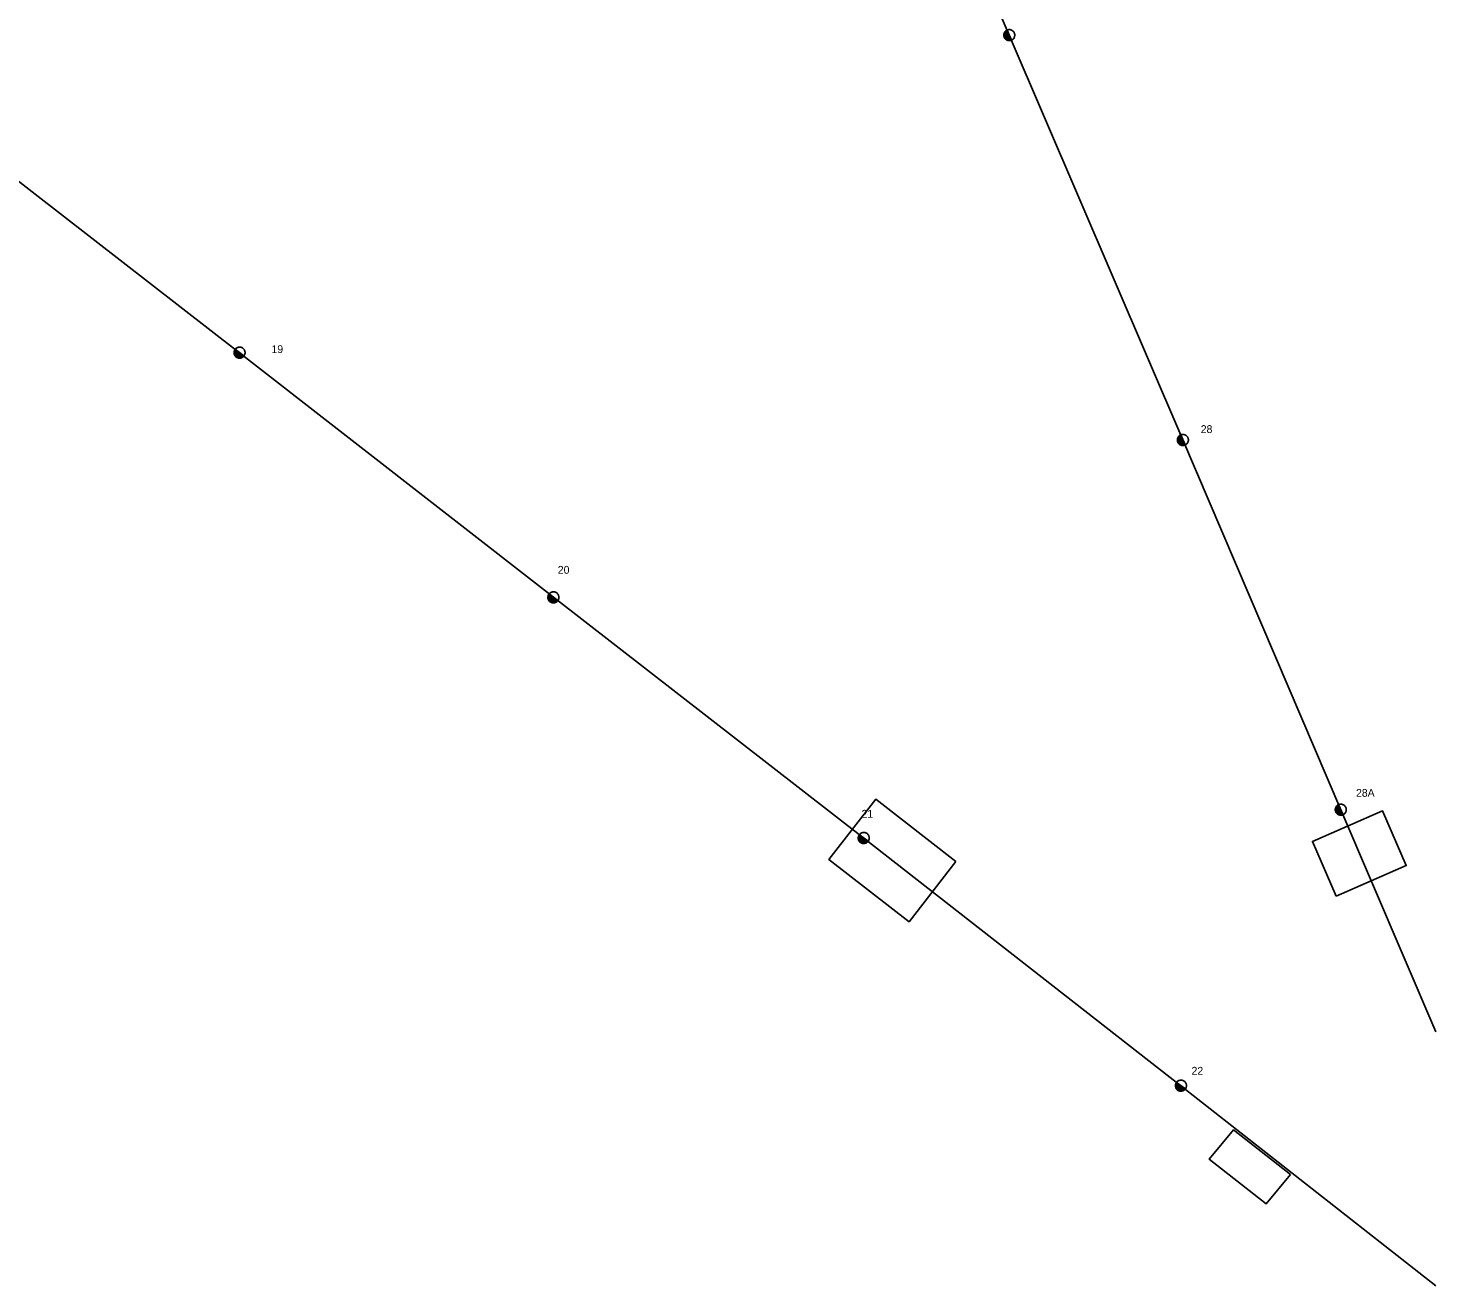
# Model space of a CAD drawing. Extents: x -762500 to -761250, y -1155000 to -1154000.
# Drawn here: x -761563.4 to -761250, y -1154560 to -1154280 of the extents above; entities that cross this region are included whole.
import ezdxf

# ---------------------------------------------------------------- set-up
doc = ezdxf.new("R2010")
doc.units = 0
for name, color, linetype in [('Vrstva 1', 7, 'Continuous'), ('Vrstva 13', 7, 'Continuous'), ('Vrstva 14', 7, 'Continuous'), ('Vrstva 35', 7, 'Continuous')]:
    doc.layers.add(name, color=color, linetype=linetype)

msp = doc.modelspace()

# ---------------------------------------------------------------- linework, layer by layer
at = {"layer": 'Vrstva 1'}
for points in [[(-761405.34, -1154140.88), (-761379.44, -1154200.97), (-761344.97, -1154281.58), (-761306.31, -1154371.71), (-761271.16, -1154454.04), (-761250, -1154503.48)], [(-761670.23, -1154232.75), (-761595.45, -1154290.91), (-761516.33, -1154352.27), (-761446.46, -1154406.74), (-761377.37, -1154460.33), (-761306.74, -1154515.48), (-761250, -1154560.04)]]:
    msp.add_lwpolyline(points, dxfattribs=at)
at = {"layer": 'Vrstva 13'}
for points in [[(-761344.477, -1154282.695), (-761344.362, -1154282.637), (-761344.255, -1154282.567), (-761344.155, -1154282.486), (-761344.064, -1154282.395), (-761343.983, -1154282.295), (-761343.913, -1154282.187), (-761343.855, -1154282.073), (-761343.808, -1154281.953), (-761343.775, -1154281.829), (-761343.755, -1154281.701), (-761343.748, -1154281.573), (-761343.755, -1154281.445), (-761343.775, -1154281.318), (-761343.808, -1154281.193), (-761343.855, -1154281.073), (-761343.913, -1154280.959), (-761343.983, -1154280.851), (-761344.064, -1154280.751), (-761344.154, -1154280.66), (-761344.254, -1154280.579), (-761344.362, -1154280.509), (-761344.477, -1154280.451), (-761344.597, -1154280.405), (-761344.721, -1154280.371), (-761344.848, -1154280.352), (-761344.976, -1154280.345), (-761345.105, -1154280.351), (-761345.232, -1154280.372), (-761345.356, -1154280.405), (-761345.476, -1154280.451), (-761345.591, -1154280.509), (-761345.699, -1154280.579), (-761345.799, -1154280.66), (-761345.89, -1154280.752), (-761345.97, -1154280.851), (-761346.04, -1154280.959), (-761346.099, -1154281.073), (-761346.145, -1154281.194), (-761346.178, -1154281.318), (-761346.199, -1154281.445), (-761346.205, -1154281.573), (-761346.198, -1154281.701), (-761346.178, -1154281.828), (-761346.145, -1154281.953), (-761346.099, -1154282.073), (-761346.041, -1154282.187), (-761345.97, -1154282.295), (-761345.889, -1154282.395), (-761345.799, -1154282.486), (-761345.699, -1154282.567), (-761345.591, -1154282.637), (-761345.476, -1154282.696), (-761345.356, -1154282.741), (-761345.232, -1154282.774), (-761345.105, -1154282.795), (-761344.977, -1154282.802), (-761344.848, -1154282.795), (-761344.721, -1154282.774), (-761344.597, -1154282.741), (-761344.477, -1154282.695)], [(-761346.109, -1154281.275), (-761345.532, -1154282.572)], [(-761345.955, -1154280.912), (-761345.151, -1154282.718)], [(-761345.762, -1154280.638), (-761344.834, -1154282.724)], [(-761345.471, -1154280.444), (-761344.471, -1154282.689)], [(-761515.359, -1154353.006), (-761515.287, -1154352.899), (-761515.226, -1154352.786), (-761515.178, -1154352.667), (-761515.142, -1154352.543), (-761515.12, -1154352.417), (-761515.112, -1154352.288), (-761515.116, -1154352.16), (-761515.133, -1154352.033), (-761515.165, -1154351.908), (-761515.209, -1154351.787), (-761515.265, -1154351.671), (-761515.333, -1154351.562), (-761515.413, -1154351.461), (-761515.502, -1154351.368), (-761515.6, -1154351.286), (-761515.707, -1154351.214), (-761515.82, -1154351.154), (-761515.94, -1154351.105), (-761516.063, -1154351.07), (-761516.19, -1154351.047), (-761516.318, -1154351.039), (-761516.447, -1154351.043), (-761516.574, -1154351.061), (-761516.699, -1154351.092), (-761516.819, -1154351.136), (-761516.935, -1154351.192), (-761517.044, -1154351.26), (-761517.146, -1154351.34), (-761517.238, -1154351.429), (-761517.321, -1154351.528), (-761517.393, -1154351.634), (-761517.453, -1154351.748), (-761517.501, -1154351.867), (-761517.536, -1154351.991), (-761517.559, -1154352.117), (-761517.568, -1154352.245), (-761517.563, -1154352.374), (-761517.545, -1154352.501), (-761517.514, -1154352.626), (-761517.47, -1154352.747), (-761517.414, -1154352.863), (-761517.346, -1154352.971), (-761517.267, -1154353.073), (-761517.177, -1154353.165), (-761517.079, -1154353.248), (-761516.972, -1154353.32), (-761516.859, -1154353.38), (-761516.739, -1154353.428), (-761516.616, -1154353.464), (-761516.49, -1154353.486), (-761516.361, -1154353.495), (-761516.232, -1154353.491), (-761516.105, -1154353.472), (-761515.98, -1154353.441), (-761515.86, -1154353.398), (-761515.744, -1154353.341), (-761515.635, -1154353.273), (-761515.534, -1154353.194), (-761515.441, -1154353.105), (-761515.359, -1154353.006)], [(-761517.516, -1154352.163), (-761515.937, -1154353.353)], [(-761517.48, -1154351.83), (-761515.656, -1154353.204)], [(-761517.474, -1154352.555), (-761516.34, -1154353.41)], [(-761517.319, -1154351.519), (-761515.357, -1154352.998)], [(-761305.818, -1154372.825), (-761305.703, -1154372.766), (-761305.595, -1154372.696), (-761305.495, -1154372.615), (-761305.404, -1154372.525), (-761305.323, -1154372.425), (-761305.253, -1154372.317), (-761305.195, -1154372.202), (-761305.149, -1154372.083), (-761305.115, -1154371.958), (-761305.095, -1154371.831), (-761305.088, -1154371.703), (-761305.096, -1154371.574), (-761305.116, -1154371.447), (-761305.149, -1154371.323), (-761305.195, -1154371.203), (-761305.253, -1154371.089), (-761305.323, -1154370.981), (-761305.404, -1154370.881), (-761305.495, -1154370.79), (-761305.595, -1154370.709), (-761305.703, -1154370.639), (-761305.817, -1154370.58), (-761305.938, -1154370.534), (-761306.062, -1154370.501), (-761306.189, -1154370.481), (-761306.317, -1154370.474), (-761306.445, -1154370.481), (-761306.573, -1154370.501), (-761306.697, -1154370.534), (-761306.817, -1154370.58), (-761306.931, -1154370.639), (-761307.039, -1154370.709), (-761307.139, -1154370.79), (-761307.23, -1154370.881), (-761307.311, -1154370.981), (-761307.381, -1154371.088), (-761307.439, -1154371.203), (-761307.485, -1154371.323), (-761307.519, -1154371.447), (-761307.539, -1154371.574), (-761307.545, -1154371.703), (-761307.539, -1154371.831), (-761307.519, -1154371.958), (-761307.485, -1154372.083), (-761307.439, -1154372.202), (-761307.381, -1154372.317), (-761307.311, -1154372.424), (-761307.23, -1154372.525), (-761307.139, -1154372.616), (-761307.039, -1154372.696), (-761306.931, -1154372.767), (-761306.817, -1154372.825), (-761306.697, -1154372.871), (-761306.572, -1154372.904), (-761306.445, -1154372.924), (-761306.317, -1154372.931), (-761306.189, -1154372.924), (-761306.062, -1154372.904), (-761305.938, -1154372.871), (-761305.818, -1154372.825)], [(-761307.45, -1154371.405), (-761306.872, -1154372.702)], [(-761307.296, -1154371.042), (-761306.492, -1154372.848)], [(-761307.103, -1154370.767), (-761306.174, -1154372.854)], [(-761306.811, -1154370.574), (-761305.812, -1154372.818)], [(-761445.489, -1154407.476), (-761445.417, -1154407.369), (-761445.356, -1154407.256), (-761445.308, -1154407.137), (-761445.272, -1154407.013), (-761445.25, -1154406.887), (-761445.242, -1154406.758), (-761445.246, -1154406.63), (-761445.263, -1154406.503), (-761445.295, -1154406.378), (-761445.339, -1154406.257), (-761445.395, -1154406.141), (-761445.463, -1154406.032), (-761445.543, -1154405.931), (-761445.632, -1154405.838), (-761445.73, -1154405.756), (-761445.837, -1154405.684), (-761445.95, -1154405.624), (-761446.07, -1154405.575), (-761446.193, -1154405.54), (-761446.32, -1154405.517), (-761446.448, -1154405.509), (-761446.577, -1154405.513), (-761446.704, -1154405.531), (-761446.829, -1154405.562), (-761446.949, -1154405.606), (-761447.065, -1154405.662), (-761447.174, -1154405.73), (-761447.276, -1154405.81), (-761447.368, -1154405.899), (-761447.451, -1154405.998), (-761447.523, -1154406.104), (-761447.583, -1154406.218), (-761447.631, -1154406.337), (-761447.666, -1154406.461), (-761447.689, -1154406.587), (-761447.698, -1154406.715), (-761447.693, -1154406.844), (-761447.675, -1154406.971), (-761447.644, -1154407.096), (-761447.6, -1154407.217), (-761447.544, -1154407.333), (-761447.476, -1154407.441), (-761447.397, -1154407.543), (-761447.307, -1154407.635), (-761447.209, -1154407.718), (-761447.102, -1154407.79), (-761446.989, -1154407.85), (-761446.869, -1154407.898), (-761446.746, -1154407.934), (-761446.62, -1154407.956), (-761446.491, -1154407.965), (-761446.362, -1154407.961), (-761446.235, -1154407.942), (-761446.11, -1154407.911), (-761445.989, -1154407.868), (-761445.874, -1154407.811), (-761445.765, -1154407.743), (-761445.664, -1154407.664), (-761445.571, -1154407.575), (-761445.489, -1154407.476)], [(-761447.646, -1154406.633), (-761446.067, -1154407.823)], [(-761447.61, -1154406.3), (-761445.786, -1154407.674)], [(-761447.604, -1154407.025), (-761446.47, -1154407.88)], [(-761447.449, -1154405.989), (-761445.487, -1154407.468)], [(-761270.667, -1154455.155), (-761270.552, -1154455.097), (-761270.445, -1154455.027), (-761270.345, -1154454.946), (-761270.254, -1154454.855), (-761270.173, -1154454.755), (-761270.103, -1154454.647), (-761270.045, -1154454.533), (-761269.998, -1154454.413), (-761269.965, -1154454.289), (-761269.945, -1154454.161), (-761269.938, -1154454.033), (-761269.945, -1154453.905), (-761269.965, -1154453.777), (-761269.998, -1154453.653), (-761270.045, -1154453.533), (-761270.103, -1154453.419), (-761270.173, -1154453.311), (-761270.254, -1154453.211), (-761270.345, -1154453.12), (-761270.445, -1154453.039), (-761270.552, -1154452.969), (-761270.667, -1154452.911), (-761270.787, -1154452.865), (-761270.912, -1154452.831), (-761271.038, -1154452.812), (-761271.166, -1154452.805), (-761271.295, -1154452.811), (-761271.422, -1154452.832), (-761271.546, -1154452.865), (-761271.666, -1154452.911), (-761271.781, -1154452.969), (-761271.889, -1154453.039), (-761271.989, -1154453.12), (-761272.08, -1154453.212), (-761272.16, -1154453.311), (-761272.23, -1154453.419), (-761272.289, -1154453.533), (-761272.335, -1154453.653), (-761272.368, -1154453.778), (-761272.389, -1154453.905), (-761272.395, -1154454.033), (-761272.388, -1154454.161), (-761272.368, -1154454.288), (-761272.335, -1154454.413), (-761272.289, -1154454.533), (-761272.231, -1154454.647), (-761272.161, -1154454.755), (-761272.079, -1154454.855), (-761271.989, -1154454.946), (-761271.889, -1154455.027), (-761271.781, -1154455.097), (-761271.666, -1154455.156), (-761271.546, -1154455.201), (-761271.422, -1154455.234), (-761271.295, -1154455.255), (-761271.167, -1154455.262), (-761271.038, -1154455.255), (-761270.911, -1154455.234), (-761270.787, -1154455.201), (-761270.667, -1154455.155)], [(-761272.299, -1154453.735), (-761271.722, -1154455.032)], [(-761272.145, -1154453.372), (-761271.341, -1154455.178)], [(-761271.953, -1154453.098), (-761271.024, -1154455.184)], [(-761271.661, -1154452.904), (-761270.662, -1154455.149)], [(-761376.399, -1154461.066), (-761376.327, -1154460.959), (-761376.267, -1154460.846), (-761376.218, -1154460.727), (-761376.183, -1154460.603), (-761376.16, -1154460.477), (-761376.152, -1154460.348), (-761376.156, -1154460.22), (-761376.174, -1154460.093), (-761376.205, -1154459.968), (-761376.249, -1154459.847), (-761376.305, -1154459.731), (-761376.373, -1154459.622), (-761376.453, -1154459.521), (-761376.542, -1154459.428), (-761376.641, -1154459.346), (-761376.747, -1154459.274), (-761376.861, -1154459.214), (-761376.98, -1154459.165), (-761377.103, -1154459.13), (-761377.23, -1154459.107), (-761377.358, -1154459.099), (-761377.487, -1154459.103), (-761377.614, -1154459.121), (-761377.739, -1154459.152), (-761377.859, -1154459.196), (-761377.975, -1154459.252), (-761378.084, -1154459.32), (-761378.186, -1154459.4), (-761378.278, -1154459.489), (-761378.361, -1154459.588), (-761378.433, -1154459.694), (-761378.493, -1154459.808), (-761378.541, -1154459.927), (-761378.576, -1154460.051), (-761378.599, -1154460.177), (-761378.608, -1154460.305), (-761378.603, -1154460.434), (-761378.585, -1154460.561), (-761378.554, -1154460.686), (-761378.511, -1154460.807), (-761378.454, -1154460.923), (-761378.386, -1154461.031), (-761378.307, -1154461.133), (-761378.217, -1154461.225), (-761378.119, -1154461.308), (-761378.012, -1154461.38), (-761377.899, -1154461.44), (-761377.78, -1154461.488), (-761377.656, -1154461.524), (-761377.53, -1154461.546), (-761377.401, -1154461.555), (-761377.272, -1154461.551), (-761377.145, -1154461.532), (-761377.02, -1154461.501), (-761376.9, -1154461.458), (-761376.784, -1154461.401), (-761376.675, -1154461.333), (-761376.574, -1154461.254), (-761376.481, -1154461.165), (-761376.399, -1154461.066)], [(-761378.556, -1154460.223), (-761376.977, -1154461.413)], [(-761378.52, -1154459.89), (-761376.696, -1154461.264)], [(-761378.514, -1154460.615), (-761377.381, -1154461.47)], [(-761378.359, -1154459.579), (-761376.397, -1154461.058)], [(-761305.769, -1154516.216), (-761305.697, -1154516.109), (-761305.636, -1154515.996), (-761305.588, -1154515.877), (-761305.552, -1154515.753), (-761305.53, -1154515.627), (-761305.522, -1154515.498), (-761305.526, -1154515.37), (-761305.543, -1154515.243), (-761305.575, -1154515.118), (-761305.619, -1154514.997), (-761305.675, -1154514.881), (-761305.743, -1154514.772), (-761305.823, -1154514.671), (-761305.912, -1154514.578), (-761306.01, -1154514.496), (-761306.117, -1154514.424), (-761306.23, -1154514.364), (-761306.35, -1154514.315), (-761306.473, -1154514.28), (-761306.6, -1154514.257), (-761306.728, -1154514.249), (-761306.857, -1154514.253), (-761306.984, -1154514.271), (-761307.109, -1154514.302), (-761307.229, -1154514.346), (-761307.345, -1154514.402), (-761307.454, -1154514.471), (-761307.556, -1154514.55), (-761307.648, -1154514.639), (-761307.731, -1154514.738), (-761307.803, -1154514.844), (-761307.863, -1154514.958), (-761307.911, -1154515.077), (-761307.946, -1154515.201), (-761307.969, -1154515.327), (-761307.978, -1154515.455), (-761307.973, -1154515.584), (-761307.955, -1154515.711), (-761307.924, -1154515.836), (-761307.88, -1154515.957), (-761307.824, -1154516.073), (-761307.756, -1154516.181), (-761307.677, -1154516.283), (-761307.587, -1154516.375), (-761307.489, -1154516.458), (-761307.382, -1154516.53), (-761307.269, -1154516.59), (-761307.149, -1154516.638), (-761307.026, -1154516.674), (-761306.9, -1154516.696), (-761306.771, -1154516.705), (-761306.642, -1154516.701), (-761306.515, -1154516.682), (-761306.39, -1154516.651), (-761306.27, -1154516.608), (-761306.154, -1154516.551), (-761306.045, -1154516.483), (-761305.944, -1154516.404), (-761305.851, -1154516.315), (-761305.769, -1154516.216)], [(-761307.926, -1154515.373), (-761306.347, -1154516.563)], [(-761307.89, -1154515.04), (-761306.066, -1154516.414)], [(-761307.884, -1154515.765), (-761306.75, -1154516.62)], [(-761307.729, -1154514.729), (-761305.767, -1154516.208)]]:
    msp.add_lwpolyline(points, dxfattribs=at)
at = {"layer": 'Vrstva 35'}
for points in [[(-761356.85, -1154465.57), (-761374.67, -1154451.66), (-761385.11, -1154465.08), (-761367.29, -1154478.99)], [(-761272.17, -1154473.28), (-761256.6, -1154466.46), (-761261.89, -1154454.26), (-761277.47, -1154461.08)], [(-761282.39, -1154535.26), (-761295.04, -1154525.33), (-761300.45, -1154531.86), (-761287.81, -1154541.79)]]:
    msp.add_lwpolyline(points, close=True, dxfattribs=at)

# ---------------------------------------------------------------- texts
at = {"layer": 'Vrstva 14'}
for s, p in [('19', (-761509.23, -1154352.36)), ('28', (-761302.34, -1154370.16)), ('20', (-761445.48, -1154401.49)), ('28A', (-761267.77, -1154451.15)), ('21', (-761377.86, -1154455.81)), ('22', (-761304.39, -1154513.03))]:
    msp.add_text(s, height=1.74, dxfattribs=at).set_placement(p)

doc.saveas('drawing.dxf')
